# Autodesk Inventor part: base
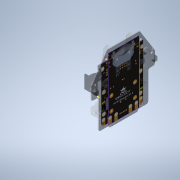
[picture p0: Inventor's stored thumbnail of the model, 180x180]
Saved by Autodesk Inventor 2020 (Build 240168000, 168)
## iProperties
Part Number: base
Material: Plastique PMMA
Document SubType Name: Modeling
Designer: Buhl
Density: 2.49798 g/cm^3
Appearance: Polycarbonate - Transparent
Mass: 86 g
Surface Area: 288.299 cm^2
Volume: 34.4278 cm^3
Author: Buhl
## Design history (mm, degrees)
sketch "Esquisse1"
  geometry: L1 (0, 0)-(78, 0); L2 (78, -3)-(78, -44); L3 (14.627, -47)-(3, -47); L4 (0, -44)-(0, -3); L5 (-3, 0)-(-8.5, 0); L6 (-11.5, 3)-(-11.5, 19.102); L7 (-11.5, 20)-(88.5, 20); L8 (88.5, 19.135)-(88.5, 3); L9 (62.948, 58)-(15.117, 58); L10 (12.611, 56.649)-(-11.006, 20.75); L11 (88.04, 20.732)-(65.487, 56.597); L12 (81, 0)-(85.5, 0); L13 (18.5, -50)-(59.768, -50); L14 (75, -47)-(63.625, -47.035); A1 r 2 centre (86.5, 19.423) between (88.5, 19.423) and (88.193, 20.488); A2 r 2 centre (63.5, 56) between (65.193, 57.065) and (63.5, 58); A3 r 2 centre (14.578, 56) between (14.578, 58) and (12.907, 57.099); A4 r 2 centre (-9.5, 19.401) between (-11.171, 20.5) and (-11.5, 19.401); A5 r 2 centre (-9.5, 2) between (-11.5, 2) and (-9.5, 0); A6 r 3 centre (85.5, 19.135) between (88.5, 19.135) and (88.04, 20.732); A7 r 3 centre (62.948, 55) between (65.487, 56.597) and (62.948, 58); A8 r 3 centre (15.117, 55) between (15.117, 58) and (12.611, 56.649); A9 r 3 centre (-8.5, 19.102) between (-11.006, 20.75) and (-11.5, 19.102); A10 r 3 centre (-8.5, 3) between (-11.5, 3) and (-8.5, 0); A11 r 3 centre (-3, -3) between (0, -3) and (-3, 0); A12 r 3 centre (3, -44) between (0, -44) and (3, -47); A13 r 3 centre (75, -44) between (75, -47) and (78, -44); A14 r 3 centre (81, -3) between (81, 0) and (78, -3); A15 r 3 centre (85.5, 3) between (85.5, 0) and (88.5, 3); A16 r 2 centre (14.627, -49) between (16.564, -48.5) and (14.627, -47); A17 r 2 centre (63.632, -49.035) between (63.625, -47.035) and (61.7, -48.518); A18 r 2 centre (18.5, -48) between (16.564, -48.5) and (18.5, -50); A19 r 2 centre (59.768, -48) between (59.768, -50) and (61.7, -48.518); 8 further points
  constraints: 38 point on circle, 36 tangent, 33 point on line, 28 end point, 19 centre point, 14 equal radius, 4 horizontal, 4 parallel, 2 perpendicular
  dimensions: "d0" = 78 distance of point (78, -47) point (0, -47); "d1" = 47 distance of L1.end point (78, -47); "d2" = 100 distance of L7.start L7.end; "d3" = 11.5 distance between parallel lines of L6 L4; "d4" = 20 distance of point (-11.5, 0) L7.start; "d5" = 105 distance between parallel lines of L3 L9; "d6" = 50 distance of point (63.5, 58) point (13.5, 58); "d7" = 25 distance from line of point (13.5, 58) L6; "d8" = 2 radius of A1 (derived); "d9" = 3 radius of A6; "d10" = 3 radius of A14 (derived); "d247" = 3 distance between parallel lines of L3 L13; "d249" = 2 radius of A16 (derived)
extrude "Extrusion1" new body sketch "Esquisse1" distance "d11" = 1.6; taper "d12" = 0 deg
sketch "Esquisse2"
  geometry: L1 (-47, 3)-(-47, 75) reference; L2 (-44, 78)-(-3, 78) reference; L3 (-47, 3)-(-47, 75) reference; L4 (-47, 39)-(32.996, 39); L5 (-50, 18.5)-(-50, 59.768) reference; L6 (0, 81)-(0, 85.5) reference; L7 (3, 88.5)-(19.135, 88.5) reference; L8 (58, 62.948)-(58, 15.117) reference; L9 (20.732, 88.04)-(56.597, 65.487) reference; C1 r 1.5 at (19.402, 83.5); C2 r 1.5 at (46, 66.244); C3 r 1.5 at (-3, 66); C4 r 1.5 at (-32, 39); 3 further points
  constraints: 4 centre point, 2 end point, 1 horizontal, 1 midpoint, 1 point on line
  dimensions: "d13" = 3 diameter of C1; "d16" = 3 diameter of C2; "d18" = 3 diameter of C3; "d255" = 3 diameter of C4; "d256" = 18 distance from line of L5 C4.centre; "d257" = 12 distance from line of L2 C3.centre; "d258" = 3 distance from line of C3.centre L6; "d259" = 5 distance from line of L7 C1.centre; "d260" = 12 distance from line of L8 C2.centre; "d261" = 5 distance from line of L9 C2.centre; "d295" = 29 horizontal distance of C4.centre C3.centre (derived)
extrude "Extrusion2" cut sketch "Esquisse2" distance "d21" = 1.6; taper "d22" = 0 deg
sketch "Esquisse3"
  geometry: C1 r 1.5 at (-3, 66) reference; C2 r 1.5 at (46, 66.244) reference; C3 r 1.5 at (19.402, 83.5) reference; C4 r 2.75 at (-3, 66); C5 r 2.75 at (46, 66.244); C6 r 1.5 at (19.402, 83.5) reference; C7 r 2.75 at (19.402, 83.5); C8 r 1.5 at (-32, 39) reference; C9 r 2.75 at (-32, 39); 1 further point
  constraints: 4 centre point, 4 coincident
  dimensions: "d23" = 5.5 diameter of C4; "d24" = 5.5 diameter of C5; "d25" = 5.5 diameter of C7; "d262" = 5.5 diameter of C9
extrude "Extrusion3" join sketch "Esquisse3" distance "d26" = 3; taper "d27" = 0 deg
sketch "Esquisse4"
  geometry: L1 (-26, 10.532)-(-32, 10.532); L2 (-32, 10.532)-(-32, 67.532); L3 (-32, 67.532)-(-26, 67.532); L4 (-26, 67.532)-(-26, 10.532); L5 (-58, 62.948)-(-58, 15.117) reference; L6 (-3.465, 3.627)-(-1.465, 3.627); L7 (-1.465, 3.627)-(-1.465, 54.627); L8 (-1.465, 54.627)-(-3.465, 54.627); L9 (-3.465, 54.627)-(-3.465, 3.627); L10 (-58, 39.032)-(-14.636, 39.032); 2 further points
  constraints: 18 end point, 4 parallel, 3 horizontal, 2 midpoint, 2 perpendicular, 1 point on line
  dimensions: "d28" = 32 distance between parallel lines of L4 L5; "d29" = 6 distance of L2.end L3.end; "d30" = 51 distance of L8.end L6.start; "d31" = 57 distance between parallel lines of L3 L1; "d32" = 2 distance between parallel lines of L7 L9
extrude "Extrusion4" join sketch "Esquisse4" distance "d33" = 12.2; taper "d34" = 0 deg
sketch "Esquisse5"
  geometry: 1 further point
sketch "Esquisse6"
  geometry: 1 further point
node "Plan de construction1"
node "Plan de construction3"
mirror "Symétrie1"
sketch "Esquisse9"
  geometry: L1 (-3, 0)-(-44, 0) reference; L2 (-32, 0)-(-17, 0); L3 (-17, 0)-(-17, 24); L4 (-17, 24)-(-32, 24); L5 (-32, 24)-(-32, 0); L6 (-47, 3)-(-47, 75) reference; 1 further point
  constraints: 8 end point, 2 parallel, 1 horizontal, 1 perpendicular, 1 point on line
  dimensions: "d54" = 15 distance of L4.end L3.end; "d55" = 24 distance of L3.end L2.end; "d56" = 15 distance between parallel lines of L6 L5
extrude "Extrusion8" join sketch "Esquisse9" distance "d57" = 11; taper "d58" = 0 deg
sketch "Esquisse10"
  geometry: L1 (0, 12)-(-11, 12) reference; L2 (0, 12)-(0, 27) reference; L3 (-11, 12)-(0, 27); C1 r 1.5 at (-5.5, 19.5); 1 further point
  constraints: 2 end point, 1 centre point, 1 midpoint
  dimensions: "d59" = 3 diameter of C1
extrude "Extrusion9" cut sketch "Esquisse10" distance "d60" = 10; taper "d61" = 0 deg
sketch "Esquisse11"
  geometry: L1 (-36, 41.532)-(-42, 41.532); L2 (-42, 41.532)-(-42, 46.532); L3 (-42, 46.532)-(-36, 46.532); L4 (-36, 46.532)-(-36, 41.532); L5 (-58, 62.948)-(-58, 15.117) reference; L6 (-15, 82.5)-(-9, 82.5); L7 (-9, 82.5)-(-9, 87.5); L8 (-9, 87.5)-(-15, 87.5); L9 (-15, 87.5)-(-15, 82.5); L10 (0, 81)-(0, 85.5) reference; L11 (-3, 88.5)-(-19.135, 88.5) reference; L12 (-61.191, 39.032)-(-11.173, 39.032); L13 (-42, 51.532)-(-36, 51.532); L14 (-36, 51.532)-(-36, 56.532); L15 (-36, 56.532)-(-42, 56.532); L16 (-42, 56.532)-(-42, 51.532); 2 further points
  constraints: 26 end point, 6 parallel, 4 horizontal, 3 perpendicular, 1 midpoint, 1 point on line
  dimensions: "d63" = 5 distance of L1.end L2.end; "d64" = 6 distance of L2.end L3.end; "d65" = 22 distance between parallel lines of L4 L5; "d271" = 6 distance of L7.end L8.end; "d272" = 5 distance of L6.end L7.end; "d273" = 9 distance between parallel lines of L10 L7; "d274" = 6 distance between parallel lines of L11 L6; "d275" = 2.5 distance between parallel lines of L1 L12; "d276" = 6 distance of L15.end L14.end; "d277" = 5 distance of L14.end L13.end; "d278" = 5 distance between parallel lines of L13 L3
extrude "Extrusion10" join sketch "Esquisse11" distance "d66" = 5; taper "d67" = 0 deg
mirror "Symétrie3"
sketch "Esquisse13"
  geometry: L1 (-52.453, 14.685)-(-52.453, 64.242); L2 (-52.453, 64.242)-(45.75, 64.242); L3 (45.75, 64.242)-(45.75, 14.685); L4 (45.75, 14.685)-(-52.453, 14.685); 1 further point; 1 other entity
  constraints: 2 other
  node "Image1"
sketch "Esquisse14"
  geometry: L1 (42.128, 71.823)-(42.128, 5.773); L2 (42.128, 5.773)-(-45.058, 5.773); L3 (-45.058, 5.773)-(-45.058, 71.823); L4 (-45.058, 71.823)-(42.128, 71.823); 1 further point; 1 other entity
  constraints: 2 end point, 1 other
  node "Image2"
sketch "Esquisse16"
  geometry: L1 (-32, 24)-(-32, 0) reference; L2 (-32, 0)-(-17, 0) reference; L3 (-32, 0)-(-29.5, 0); L4 (-29.5, 0)-(-29.5, 7); L5 (-29.5, 7)-(-32, 7); L6 (-32, 7)-(-32, 0); L7 (-17, 0)-(-19.5, 0); L8 (-19.5, 0)-(-19.5, 7); L9 (-19.5, 7)-(-17, 7); L10 (-17, 7)-(-17, 0); L11 (-32, 54)-(-32, 78) reference; L12 (-32, 78)-(-17, 78) reference; L13 (-17, 78)-(-17, 54) reference; L14 (-32, 78)-(-29.5, 78); L15 (-29.5, 78)-(-29.5, 71); L16 (-29.5, 71)-(-32, 71); L17 (-32, 71)-(-32, 78); L18 (-17, 78)-(-19.5, 78); L19 (-19.5, 78)-(-19.5, 71); L20 (-19.5, 71)-(-17, 71); L21 (-17, 71)-(-17, 78); 1 further point
  constraints: 32 end point, 8 parallel, 4 horizontal, 4 perpendicular, 2 point on line
  dimensions: "d186" = 2.5 distance of L4.end L5.end; "d187" = 2.5 distance of L8.end L9.end; "d188" = 7 distance of L3.end L4.end; "d189" = 7 distance of L18.end L19.end
extrude "Extrusion13" cut sketch "Esquisse16" distance "d190" = 11; taper "d191" = 0 deg
node "Plan de construction2"
sketch "Esquisse12"
  geometry: C1 r 1.683 at (-14.287, 36.5); C2 r 1.703 at (-9.745, 36.5); 1 further point
  constraints: 2 centre point
extrude "Extrusion11" cut sketch "Esquisse12" distance "d68" = 0.5; taper "d69" = 0 deg
mirror "Symétrie2"
sketch "Esquisse17"
  geometry: L1 (-44, 78)-(-3, 78) reference; L2 (-3, 0)-(-44, 0) reference; L3 (0, 78)-(20, 78); L4 (20, 78)-(20, 0); L5 (20, 0)-(0, 0); L6 (0, 0)-(0, 78); 3 further points
  constraints: 8 end point, 2 parallel, 1 horizontal, 1 perpendicular
  dimensions: "d222" = 20 distance of L4.end L5.end
extrude "Extrusion14" join sketch "Esquisse17" distance "d223" = 21; taper "d224" = 0 deg
sketch "Esquisse18"
  geometry: L1 (0, 0)-(0, 78) reference; L2 (0, 0)-(21, 0) reference; L3 (21, 78)-(21, 0) reference; L4 (0, 78)-(21, 78) reference; L5 (22.117, 76.165)-(15.78, 76.165); L6 (15.78, 1.988)-(22.117, 1.988); L7 (22.117, 1.988)-(22.117, 76.165); L8 (0, 24)-(11, 24) reference; L9 (8.573, 52.434)-(8.573, 24); L10 (8.573, 24)-(13.171, 24); L11 (13.171, 52.434)-(13.171, 64.289); L12 (13.171, 64.289)-(15.78, 69.704); L13 (13.171, 24)-(13.171, 13.419); L14 (13.171, 13.419)-(15.78, 7.082); L15 (15.78, 76.165)-(15.78, 69.704); L16 (15.78, 7.082)-(15.78, 1.988); L17 (13.171, 52.434)-(8.573, 52.434); 2 further points
  constraints: 24 end point, 4 parallel, 3 perpendicular, 2 horizontal, 2 point on line, 1 vertical
extrude "Extrusion15" cut sketch "Esquisse18" distance "d265" = 20; taper "d266" = 0 deg
sketch "Esquisse19"
  geometry: L1 (21, 20)-(0, 20) reference; L2 (0, 20)-(21, 0); L3 (0, 0)-(21, 20); C1 r 9.355 at (9.339, 10)
  constraints: 4 end point, 1 centre point
extrude "Extrusion16" cut sketch "Esquisse19" stored distance "d267" = 20; taper "d268" = 0 deg
sketch "Esquisse20"
  geometry: L1 (30.205, 66.59)-(27.421, 66.59); L2 (27.421, 66.59)-(27.421, 11.814); L3 (27.421, 11.814)-(30.205, 11.814); L4 (30.205, 11.814)-(30.205, 66.59); 1 further point
  constraints: 8 end point, 2 parallel, 1 horizontal, 1 perpendicular
extrude "Extrusion17" cut sketch "Esquisse20" distance "d269" = 10; taper "d270" = 0 deg
mirror "Symétrie4"
node "Plan de construction5"
sketch "Esquisse22"
  geometry: L1 (0, -26.617)-(1.6, -26.617) reference; L2 (0, 73.383)-(1.6, 73.383) reference; C1 r 5 at (-5.411, 5.383); C2 r 5 at (-5.411, 41.383); 1 further point
  constraints: 2 centre point
  dimensions: "d280" = 10 diameter of C1; "d281" = 10 diameter of C2; "d282" = 32 distance from line of L1 C1.centre; "d283" = 32 distance from line of C2.centre L2
extrude "Extrusion18" join sketch "Esquisse22" distance "d284" = 2; taper "d285" = 0 deg
sketch "Esquisse23"
  geometry: C1 r 4.5 at (0, 0); C2 r 5 at (0, 36) reference; C3 r 4.5 at (0, 36); 1 further point
  constraints: 2 centre point, 1 coincident
  dimensions: "d286" = 9 diameter of C1; "d287" = 9 diameter of C3
extrude "Extrusion19" join sketch "Esquisse23" distance "d288" = 11; taper "d289" = 0 deg
fillet "Congé1" dims "d290" = 4.5
node "Solide1"
node "Boucle projetée4"
node "Plan de construction4"
node "Boucle projetée5"
other parameters: "d35" = -39, "d231" = -39, "d279" = -15
